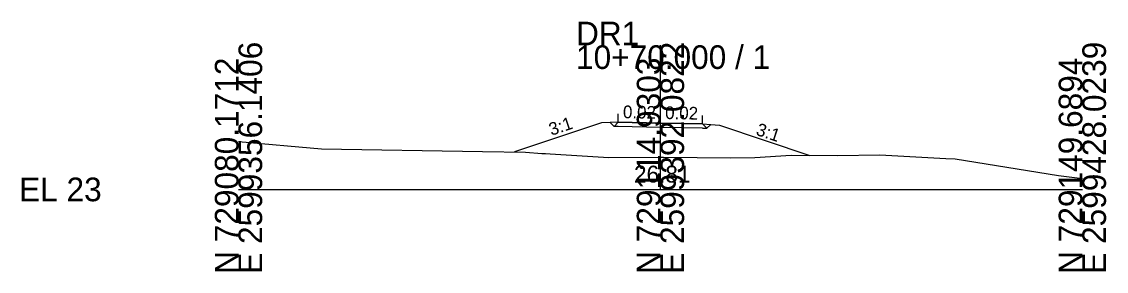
# Model space of a CAD drawing. Extents: x -26 to 1162, y -10 to 9515.
# Drawn here: x -25.7 to 102.8, y 3490.3 to 3519.9 of the extents above; entities that cross this region are included whole.
import ezdxf

# ---------------------------------------------------------------- set-up
doc = ezdxf.new("R2010")
doc.units = 0
for name, color, linetype in [('Exist Cross Section Cell', 7, 'Continuous'), ('Exist XS Center Line Elevation Label', 7, 'Continuous'), ('Exist XS Ground Line', 7, 'Continuous'), ('Prop XS Ditch Slope Text', 7, 'Continuous'), ('Prop XS Dump Level', 7, 'Continuous'), ('Prop XS EOT Tick Mark', 7, 'Continuous'), ('Prop XS Finish Grade', 7, 'Continuous'), ('Prop XS Finish Grade Earthwork', 7, 'Continuous'), ('Prop XS Finish Grade Pavement', 7, 'Continuous'), ('Prop XS Pvmt Edge Slope', 7, 'Continuous'), ('Prop XS SE Text', 7, 'Continuous'), ('Prop XS Subgrade Earthwork', 7, 'Continuous')]:
    doc.layers.add(name, color=color, linetype=linetype)

msp = doc.modelspace()

# ---------------------------------------------------------------- linework, layer by layer
at = {"layer": 'Exist Cross Section Cell'}
for p, q in [((50, 3500), (50, 3517.06)), ((0, 3500), (50, 3500)), ((50, 3500), (100, 3500))]:
    msp.add_line(p, q, dxfattribs=at)
at = {"layer": 'Exist XS Ground Line'}
msp.add_lwpolyline([(0, 3505.69), (9.84, 3504.8), (28.91, 3504.48), (34.02, 3504.42), (35.95, 3504.27), (36.37, 3504.25), (36.93, 3504.23), (43.9, 3503.77), (50, 3503.81), (50.36, 3503.81), (58.33, 3503.74), (61.17, 3503.77), (65.5, 3504.04), (71, 3504.01), (76.01, 3504.1), (83.82, 3503.68), (84.91, 3503.61), (97.18, 3501.65), (100, 3501.31)], dxfattribs=at)
at = {"layer": 'Prop XS Dump Level'}
for p, q in [((50, 3507.85), (45, 3507.95)), ((45, 3507.95), (50, 3507.85)), ((55, 3507.75), (50, 3507.85)), ((50, 3507.85), (55, 3507.75))]:
    msp.add_line(p, q, dxfattribs=at)
at = {"layer": 'Prop XS EOT Tick Mark'}
for p, q in [((45, 3507.95), (45, 3508.95)), ((55, 3507.75), (55, 3508.75))]:
    msp.add_line(p, q, dxfattribs=at)
at = {"layer": 'Prop XS Finish Grade'}
for p, q in [((45, 3507.95), (44.06, 3507.92)), ((55, 3507.75), (55.98, 3507.67))]:
    msp.add_line(p, q, dxfattribs=at)
at = {"layer": 'Prop XS Finish Grade Earthwork'}
for p, q in [((43, 3507.87), (32.7, 3504.44)), ((44.06, 3507.92), (43, 3507.87)), ((55.98, 3507.67), (57, 3507.59)), ((57, 3507.59), (67.7, 3504.03))]:
    msp.add_line(p, q, dxfattribs=at)
at = {"layer": 'Prop XS Finish Grade Pavement'}
for p, q in [((45, 3507.95), (50, 3507.85)), ((50, 3507.85), (55, 3507.75))]:
    msp.add_line(p, q, dxfattribs=at)
at = {"layer": 'Prop XS Pvmt Edge Slope'}
for p, q in [((44.06, 3507.92), (44.51, 3507.46)), ((45, 3507.95), (44.51, 3507.46)), ((55, 3507.75), (55.51, 3507.24)), ((55.98, 3507.67), (55.51, 3507.24))]:
    msp.add_line(p, q, dxfattribs=at)
at = {"layer": 'Prop XS Subgrade Earthwork'}
for p, q in [((44.51, 3507.46), (44.06, 3507.92)), ((44.51, 3507.46), (44.06, 3507.92)), ((55.51, 3507.24), (55.98, 3507.67)), ((55.51, 3507.24), (55.98, 3507.67)), ((45, 3507.45), (44.51, 3507.46)), ((50, 3507.35), (45, 3507.45)), ((55, 3507.25), (50, 3507.35)), ((55, 3507.25), (55.51, 3507.24))]:
    msp.add_line(p, q, dxfattribs=at)

# ---------------------------------------------------------------- texts
at = {"layer": 'Exist Cross Section Cell'}
for s, p in [('DR1', (40, 3517.06)), ('10+70.000 / 1', (40, 3514.26)), ('EL 23', (-26, 3498.6))]:
    msp.add_text(s, height=2.8, dxfattribs=at).set_placement(p)
for s, p in [('E 2599356.1406', (2.8, 3490)), ('E 2599392.0822', (52.8, 3490)), ('E 2599428.0239', (102.8, 3490)), ('N 729080.1712', (0, 3490)), ('N 729114.9303', (50, 3490)), ('N 729149.6894', (100, 3490))]:
    msp.add_text(s, height=2.8, rotation=90, dxfattribs=at).set_placement(p)
at = {"layer": 'Exist XS Center Line Elevation Label'}
msp.add_text('26.81', height=2, dxfattribs=at).set_placement((46.87, 3500.81))
at = {"layer": 'Prop XS Ditch Slope Text'}
for rotation, p in [(18.4349, (37.08, 3506.34)), (341.5883, (61.23, 3506.48))]:
    msp.add_text('3:1', height=1.5, rotation=rotation, dxfattribs=at).set_placement(p)
at = {"layer": 'Prop XS Dump Level'}
for p in [(43, 3507.83), (57, 3507.55)]:
    msp.add_text('Case1', height=0.04, dxfattribs=at).set_placement(p)
at = {"layer": 'Prop XS SE Text'}
for p in [(45.55, 3508.44), (50.55, 3508.34)]:
    msp.add_text('0.02', height=1.5, rotation=358.8542, dxfattribs=at).set_placement(p)

doc.saveas('drawing.dxf')
